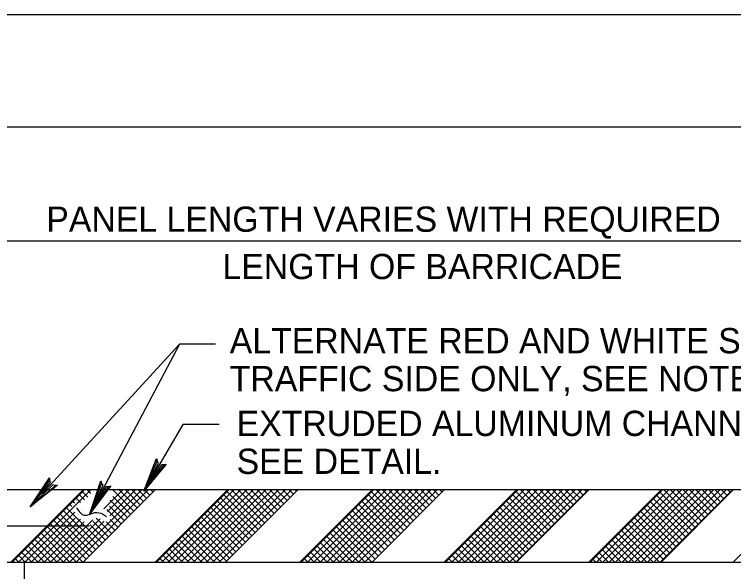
# Model space of a CAD drawing. Extents: x -4 to 901, y -468 to 720.
# Drawn here: x 421.8 to 517.4, y 645.9 to 720 of the extents above; entities that cross this region are included whole.
import ezdxf

# ---------------------------------------------------------------- set-up
doc = ezdxf.new("R2010")
doc.units = 0
for name, color, linetype in [('1', 7, 'Continuous'), ('2', 7, 'Continuous'), ('3', 7, 'Continuous'), ('PLT-BNDY', 7, 'Continuous')]:
    doc.layers.add(name, color=color, linetype=linetype)

msp = doc.modelspace()

# ---------------------------------------------------------------- linework, layer by layer
at = {"layer": '1'}
msp.add_lwpolyline([(822.258, 141.027875), (822.258, 705.027875), (36.258, 705.027875), (36.258, 141.027875), (822.258, 141.027875), (822.258, 167.386875), (622.258, 167.386875), (622.258, 232.064375), (822.258, 232.064375), (822.258, 261.027875), (622.258, 261.027875), (622.258, 141.027875), (701.0595, 141.027875), (701.0595, 167.386875), (701.0595, 141.027875), (778.0595, 141.027875), (778.0595, 167.386875), (778.0595, 155.070375), (822.258, 155.070375)], dxfattribs=at)
at = {"layer": '2'}
for p, q in [((549.1045, 689.865125), (405.1045, 689.865125)), ((421.3385, 647.195125), (430.9385, 656.795125)), ((424.3045, 650.161125), (430.9385, 656.795125)), ((430.9385, 647.195125), (440.5385, 656.795125)), ((430.9385, 647.195125), (440.5385, 656.795125)), ((440.5385, 647.195125), (450.1385, 656.795125)), ((441.38725, 647.195125), (450.98725, 656.795125)), ((442.23575, 647.195125), (451.83575, 656.795125)), ((443.08425, 647.195125), (452.68425, 656.795125)), ((443.93275, 647.195125), (453.53275, 656.795125)), ((444.78125, 647.195125), (454.38125, 656.795125)), ((445.62975, 647.195125), (455.22975, 656.795125)), ((446.47825, 647.195125), (456.07825, 656.795125)), ((447.32675, 647.195125), (456.92675, 656.795125)), ((448.17525, 647.195125), (457.77525, 656.795125)), ((449.02375, 647.195125), (458.62375, 656.795125)), ((449.87225, 647.195125), (459.47225, 656.795125)), ((459.7385, 647.195125), (469.3385, 656.795125)), ((469.3385, 647.195125), (478.9385, 656.795125)), ((469.3385, 647.195125), (478.9385, 656.795125)), ((469.3385, 647.195125), (478.9385, 656.795125)), ((469.3385, 647.195125), (478.9385, 656.795125)), ((478.9385, 647.195125), (488.5385, 656.795125)), ((481.9045, 650.161125), (488.5385, 656.795125)), ((488.5385, 647.195125), (498.1385, 656.795125)), ((488.5385, 647.195125), (498.1385, 656.795125)), ((488.5385, 647.195125), (498.1385, 656.795125)), ((488.5385, 647.195125), (498.1385, 656.795125)), ((488.5385, 647.195125), (498.1385, 656.795125)), ((498.1385, 647.195125), (507.7385, 656.795125)), ((501.1045, 650.161125), (507.7385, 656.795125)), ((507.7385, 647.195125), (517.3385, 656.795125)), ((507.7385, 647.195125), (517.3385, 656.795125)), ((507.7385, 647.195125), (517.3385, 656.795125)), ((507.7385, 647.195125), (517.3385, 656.795125)), ((507.7385, 647.195125), (517.3385, 656.795125)), ((507.7385, 647.195125), (517.3385, 656.795125)), ((517.3385, 647.195125), (526.9385, 656.795125)), ((431.7345, 651.995125), (397.6465, 651.995125))]:
    msp.add_line(p, q, dxfattribs=at)
for points in [[(443.7465, 676.169125), (425.5065, 656.291125)], [(448.5465, 676.169125), (443.7465, 676.169125), (431.8145, 653.625125)], [(449.0125, 665.477125), (444.2125, 665.477125), (439.0185, 656.647125)], [(441.7005, 660.127125), (441.3465, 660.147125), (439.0185, 656.647125), (441.7005, 660.127125), (441.9785, 660.223125), (439.0185, 656.647125), (440.9665, 660.367125), (440.7745, 660.657125), (439.0185, 656.647125), (440.7145, 660.965125), (440.7745, 660.657125)], [(427.2625, 657.397125), (426.9205, 657.489125), (423.9125, 654.555125), (427.2625, 657.397125), (427.5545, 657.431125), (423.9125, 654.555125), (426.5945, 657.785125), (426.4685, 658.109125), (423.9125, 654.555125), (426.4745, 658.423125), (426.4685, 658.109125)], [(434.3365, 657.221125), (433.9825, 657.225125), (431.8145, 653.625125), (434.3365, 657.221125), (434.6105, 657.329125), (431.8145, 653.625125), (433.5925, 657.429125), (433.3885, 657.709125), (431.8145, 653.625125), (433.3145, 658.015125), (433.3885, 657.709125)], [(421.51475, 647.195125), (431.11475, 656.795125)], [(422.36325, 647.195125), (431.96325, 656.795125)], [(429.15175, 647.195125), (438.75175, 656.795125)], [(430.00025, 647.195125), (439.60025, 656.795125)], [(431.573, 655.850875), (430.7835, 656.640375)], [(431.949, 656.323375), (431.47725, 656.795125)], [(433.69425, 654.283625), (436.20575, 656.795125)], [(434.183, 653.923875), (437.05425, 656.795125)], [(434.478, 653.370375), (437.90275, 656.795125)], [(437.683, 653.983375), (434.87125, 656.795125)], [(438.10725, 654.407625), (435.71975, 656.795125)], [(438.5315, 654.831875), (436.56825, 656.795125)], [(438.95575, 655.256125), (437.41675, 656.795125)], [(439.38, 655.680375), (438.26525, 656.795125)], [(439.80425, 656.104625), (439.11375, 656.795125)], [(440.2285, 656.528875), (439.96225, 656.795125)], [(440.71475, 647.195125), (450.31475, 656.795125)], [(454.6505, 651.973375), (449.9835, 656.640375)], [(455.07475, 652.397625), (450.67725, 656.795125)], [(455.499, 652.821875), (451.52575, 656.795125)], [(455.92325, 653.246125), (452.37425, 656.795125)], [(456.3475, 653.670375), (453.22275, 656.795125)], [(456.77175, 654.094625), (454.07125, 656.795125)], [(457.196, 654.518875), (454.91975, 656.795125)], [(457.62025, 654.943125), (455.76825, 656.795125)], [(458.0445, 655.367375), (456.61675, 656.795125)], [(458.46875, 655.791625), (457.46525, 656.795125)], [(458.893, 656.215875), (458.31375, 656.795125)], [(459.31725, 656.640125), (459.16225, 656.795125)], [(459.91475, 647.195125), (469.51475, 656.795125)], [(460.76325, 647.195125), (470.36325, 656.795125)], [(461.61175, 647.195125), (471.21175, 656.795125)], [(462.46025, 647.195125), (472.06025, 656.795125)], [(463.30875, 647.195125), (472.90875, 656.795125)], [(464.15725, 647.195125), (473.75725, 656.795125)], [(465.00575, 647.195125), (474.60575, 656.795125)], [(465.85425, 647.195125), (475.45425, 656.795125)], [(466.70275, 647.195125), (476.30275, 656.795125)], [(467.55175, 647.195125), (477.15175, 656.795125)], [(468.40025, 647.195125), (478.00025, 656.795125)], [(473.96175, 651.862125), (469.1835, 656.640375)], [(474.386, 652.286375), (469.87725, 656.795125)], [(474.81025, 652.710625), (470.72575, 656.795125)], [(475.2345, 653.134875), (471.57425, 656.795125)], [(475.65875, 653.559125), (472.42275, 656.795125)], [(476.083, 653.983375), (473.27125, 656.795125)], [(476.50725, 654.407625), (474.11975, 656.795125)], [(476.9315, 654.831875), (474.96825, 656.795125)], [(477.35575, 655.256125), (475.81675, 656.795125)], [(477.78, 655.680375), (476.66525, 656.795125)], [(478.20425, 656.104625), (477.51375, 656.795125)], [(478.6285, 656.528875), (478.36225, 656.795125)], [(479.11475, 647.195125), (488.71475, 656.795125)], [(479.96325, 647.195125), (489.56325, 656.795125)], [(480.81175, 647.195125), (490.41175, 656.795125)], [(481.66025, 647.195125), (491.26025, 656.795125)], [(482.50875, 647.195125), (492.10875, 656.795125)], [(483.35725, 647.195125), (492.95725, 656.795125)], [(484.20575, 647.195125), (493.80575, 656.795125)], [(485.05425, 647.195125), (494.65425, 656.795125)], [(485.90275, 647.195125), (495.50275, 656.795125)], [(486.75175, 647.195125), (496.35175, 656.795125)], [(487.60025, 647.195125), (497.20025, 656.795125)], [(493.16175, 651.862125), (488.3835, 656.640375)], [(488.44875, 647.195125), (498.04875, 656.795125)], [(493.586, 652.286375), (489.07725, 656.795125)], [(494.01025, 652.710625), (489.92575, 656.795125)], [(494.4345, 653.134875), (490.77425, 656.795125)], [(494.85875, 653.559125), (491.62275, 656.795125)], [(495.283, 653.983375), (492.47125, 656.795125)], [(495.70725, 654.407625), (493.31975, 656.795125)], [(496.1315, 654.831875), (494.16825, 656.795125)], [(496.55575, 655.256125), (495.01675, 656.795125)], [(496.98, 655.680375), (495.86525, 656.795125)], [(497.40425, 656.104625), (496.71375, 656.795125)], [(497.8285, 656.528875), (497.56225, 656.795125)], [(498.31475, 647.195125), (507.91475, 656.795125)], [(499.16325, 647.195125), (508.76325, 656.795125)], [(500.01175, 647.195125), (509.61175, 656.795125)], [(500.86025, 647.195125), (510.46025, 656.795125)], [(501.70875, 647.195125), (511.30875, 656.795125)], [(502.55725, 647.195125), (512.15725, 656.795125)], [(503.40575, 647.195125), (513.00575, 656.795125)], [(504.25425, 647.195125), (513.85425, 656.795125)], [(505.10275, 647.195125), (514.70275, 656.795125)], [(505.95175, 647.195125), (515.55175, 656.795125)], [(506.80025, 647.195125), (516.40025, 656.795125)], [(507.64875, 647.195125), (517.24875, 656.795125)], [(512.737, 652.193875), (508.13575, 656.795125)], [(513.16125, 652.618125), (508.98425, 656.795125)], [(513.5855, 653.042375), (509.83275, 656.795125)], [(514.00975, 653.466625), (510.68125, 656.795125)], [(514.434, 653.890875), (511.52975, 656.795125)], [(514.85825, 654.315125), (512.37825, 656.795125)], [(515.2825, 654.739375), (513.22675, 656.795125)], [(515.70675, 655.163625), (514.07525, 656.795125)], [(516.131, 655.587875), (514.92375, 656.795125)], [(516.55525, 656.012125), (515.77225, 656.795125)], [(516.9795, 656.436375), (516.62075, 656.795125)], [(430.612, 655.114875), (429.935, 655.791875)], [(431.1165, 655.458875), (430.35925, 656.216125)], [(437.25875, 653.559125), (434.89875, 655.919125)], [(453.802, 651.124875), (449.135, 655.791875)], [(454.22625, 651.549125), (449.55925, 656.216125)], [(473.11325, 651.013625), (468.335, 655.791875)], [(473.5375, 651.437875), (468.75925, 656.216125)], [(492.31325, 651.013625), (487.535, 655.791875)], [(492.7375, 651.437875), (487.95925, 656.216125)], [(511.464, 650.920875), (506.664, 655.720875)], [(511.8885, 651.345375), (507.0885, 656.145375)], [(512.31275, 651.769625), (507.51275, 656.569625)], [(429.4245, 654.604875), (429.08625, 654.943125)], [(429.84875, 655.029125), (429.5105, 655.367375)], [(436.8345, 653.134875), (434.555, 655.414375)], [(452.95325, 650.276125), (448.28625, 654.943125)], [(453.3775, 650.700375), (448.7105, 655.367375)], [(472.2645, 650.164875), (467.48625, 654.943125)], [(472.68875, 650.589125), (467.9105, 655.367375)], [(491.4645, 650.164875), (486.68625, 654.943125)], [(491.88875, 650.589125), (487.1105, 655.367375)], [(510.6155, 650.072375), (505.8155, 654.872375)], [(511.03975, 650.496625), (506.23975, 655.296625)], [(423.21175, 647.195125), (429.8365, 653.819875)], [(433.016, 649.316375), (428.23775, 654.094625)], [(433.44025, 649.740625), (428.662, 654.518875)], [(435.986, 652.286375), (434.0775, 654.194875)], [(436.41025, 652.710625), (434.4695, 654.651375)], [(452.10475, 649.427625), (447.43775, 654.094625)], [(452.529, 649.851875), (447.862, 654.518875)], [(471.416, 649.316375), (466.63775, 654.094625)], [(471.84025, 649.740625), (467.062, 654.518875)], [(490.616, 649.316375), (485.83775, 654.094625)], [(491.04025, 649.740625), (486.262, 654.518875)], [(509.767, 649.223875), (504.967, 654.023875)], [(510.19125, 649.648125), (505.39125, 654.448125)], [(424.06025, 647.195125), (429.89, 653.024875)], [(424.90875, 647.195125), (430.6045, 652.890875)], [(426.60575, 647.195125), (432.227, 652.816375)], [(431.74325, 648.043625), (426.965, 652.821875)], [(432.1675, 648.467875), (427.38925, 653.246125)], [(427.45425, 647.195125), (433.1995, 652.940375)], [(432.59175, 648.892125), (427.8135, 653.670375)], [(434.71325, 651.013625), (432.692, 653.034875)], [(435.56175, 651.862125), (434.55625, 652.867625)], [(450.832, 648.154875), (446.165, 652.821875)], [(451.25625, 648.579125), (446.58925, 653.246125)], [(451.6805, 649.003375), (447.0135, 653.670375)], [(470.14325, 648.043625), (465.365, 652.821875)], [(470.5675, 648.467875), (465.78925, 653.246125)], [(470.99175, 648.892125), (466.2135, 653.670375)], [(489.34325, 648.043625), (484.565, 652.821875)], [(489.7675, 648.467875), (484.98925, 653.246125)], [(490.19175, 648.892125), (485.4135, 653.670375)], [(508.9185, 648.375375), (504.1185, 653.175375)], [(509.34275, 648.799625), (504.54275, 653.599625)], [(425.75725, 647.195125), (431.09325, 652.531125)], [(430.89475, 647.195125), (426.1165, 651.973375)], [(431.319, 647.619375), (426.54075, 652.397625)], [(428.30275, 647.195125), (433.7525, 652.644875)], [(433.8645, 650.164875), (431.8755, 652.153875)], [(434.28875, 650.589125), (432.2835, 652.594375)], [(435.1375, 651.437875), (434.019, 652.556375)], [(449.9835, 647.306375), (445.3165, 651.973375)], [(450.40775, 647.730625), (445.74075, 652.397625)], [(469.29475, 647.195125), (464.5165, 651.973375)], [(469.719, 647.619375), (464.94075, 652.397625)], [(488.49475, 647.195125), (483.7165, 651.973375)], [(488.919, 647.619375), (484.14075, 652.397625)], [(507.55325, 647.195125), (502.84575, 651.902625)], [(508.07, 647.526875), (503.27, 652.326875)], [(508.49425, 647.951125), (503.69425, 652.751125)], [(429.19775, 647.195125), (425.268, 651.124875)], [(430.04625, 647.195125), (425.69225, 651.549125)], [(448.39775, 647.195125), (444.468, 651.124875)], [(449.24625, 647.195125), (444.89225, 651.549125)], [(467.59775, 647.195125), (463.668, 651.124875)], [(468.44625, 647.195125), (464.09225, 651.549125)], [(486.79775, 647.195125), (482.868, 651.124875)], [(487.64625, 647.195125), (483.29225, 651.549125)], [(505.85625, 647.195125), (501.99725, 651.054125)], [(506.70475, 647.195125), (502.4215, 651.478375)], [(427.50075, 647.195125), (424.4195, 650.276375)], [(428.34925, 647.195125), (424.84375, 650.700625)], [(446.70075, 647.195125), (443.6195, 650.276375)], [(447.54925, 647.195125), (444.04375, 650.700625)], [(465.90075, 647.195125), (462.8195, 650.276375)], [(466.74925, 647.195125), (463.24375, 650.700625)], [(485.10075, 647.195125), (482.0195, 650.276375)], [(485.94925, 647.195125), (482.44375, 650.700625)], [(504.15925, 647.195125), (501.14875, 650.205625)], [(505.00775, 647.195125), (501.573, 650.629875)], [(424.95525, 647.195125), (423.14675, 649.003625)], [(425.80375, 647.195125), (423.571, 649.427875)], [(426.65225, 647.195125), (423.99525, 649.852125)], [(444.15525, 647.195125), (442.34675, 649.003625)], [(445.00375, 647.195125), (442.771, 649.427875)], [(445.85225, 647.195125), (443.19525, 649.852125)], [(463.35525, 647.195125), (461.54675, 649.003625)], [(464.20375, 647.195125), (461.971, 649.427875)], [(465.05225, 647.195125), (462.39525, 649.852125)], [(482.55525, 647.195125), (480.74675, 649.003625)], [(483.40375, 647.195125), (481.171, 649.427875)], [(484.25225, 647.195125), (481.59525, 649.852125)], [(502.46225, 647.195125), (500.30025, 649.357125)], [(503.31075, 647.195125), (500.7245, 649.781375)], [(423.25775, 647.195125), (422.298, 648.154875)], [(424.10675, 647.195125), (422.7225, 648.579375)], [(442.45775, 647.195125), (441.498, 648.154875)], [(443.30675, 647.195125), (441.9225, 648.579375)], [(461.65775, 647.195125), (460.698, 648.154875)], [(462.50675, 647.195125), (461.1225, 648.579375)], [(480.85775, 647.195125), (479.898, 648.154875)], [(481.70675, 647.195125), (480.3225, 648.579375)], [(499.91625, 647.195125), (499.02725, 648.084125)], [(500.76475, 647.195125), (499.4515, 648.508375)], [(501.61375, 647.195125), (499.876, 648.932875)], [(422.40925, 647.195125), (421.87375, 647.730625)], [(423.1045, 647.195125), (423.1045, 637.595125)], [(441.60925, 647.195125), (441.07375, 647.730625)], [(460.80925, 647.195125), (460.27375, 647.730625)], [(479.16075, 647.195125), (479.0495, 647.306375)], [(480.00925, 647.195125), (479.47375, 647.730625)], [(499.06775, 647.195125), (498.603, 647.659875)]]:
    msp.add_lwpolyline(points, dxfattribs=at)
msp.add_lwpolyline([(405.1045, 656.795125), (405.1045, 647.195125), (549.1045, 647.195125), (549.1045, 656.795125)], close=True, dxfattribs=at)
msp.add_spline([(430.0485, 654.471125), (431.0925, 653.425125), (432.4865, 653.773125), (433.5305, 653.599125), (434.0525, 653.251125)], degree=3, dxfattribs=at)
at = {"layer": 'PLT-BNDY'}
msp.add_lwpolyline([(-3.742, 720.027875), (837.258, 720.027875), (837.258, 126.027875), (-3.742, 126.027875)], close=True, dxfattribs=at)

# ---------------------------------------------------------------- texts
at = {"layer": '3'}
for s, p in [('PANEL LENGTH VARIES WITH REQUIRED', (426.0505, 691.117125)), ('LENGTH OF BARRICADE', (449.4605, 684.825125)), ('ALTERNATE RED AND WHITE STRIPES,', (450.4265, 674.959125)), ('TRAFFIC SIDE ONLY, SEE NOTE 1.', (450.4265, 669.919125)), ('EXTRUDED ALUMINUM CHANNEL,', (451.3425, 663.965125)), ('SEE DETAIL.', (451.3425, 658.925125))]:
    msp.add_text(s, height=3.359988, dxfattribs=at).set_placement(p)

doc.saveas('drawing.dxf')
